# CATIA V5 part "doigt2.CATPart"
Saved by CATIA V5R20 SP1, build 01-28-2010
Part number: doigt2
Bounding box of the stored display mesh (mm): x -20 to -3, y -206.5 to -61.5, z -6 to 36.5
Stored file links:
  D:\thinkmotion-MPB\Dropbox\IAO_2011\MMS_GR1\0\IAO_2011_1470_mpeyrard\mpeyrard\mpeyrard\mpeyrard\IAO_2011_1470_mpeyrard\doigt2.CATPart
  D:\thinkmotion-MPB\Dropbox\IAO_2011\MMS_GR1\0\IAO_2011_1470_mpeyrard\mpeyrard\mpeyrard\mpeyrard\IAO_2011_1470_mpeyrard\mpeyrard.CATProduct
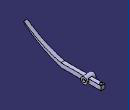
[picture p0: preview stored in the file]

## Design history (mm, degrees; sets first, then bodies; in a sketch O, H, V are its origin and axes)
External parameters (linked from other documents)
  External.Longueur_griffe = 70 mm
  External.Hauteur_griffe = 30 mm
Set1
  Line1: linked copy from another document
  Plane1: linked copy from another document
  Line2: linked copy from another document
  Line3: linked copy from another document
Body1 (main body)
  Sketch1 on yz-plane, origin (0, 0, 0), H (0, 1, 0), V (0, 0, 1)
    circle A1 centre (-90, 0) radius 6
    point P1 (-90, 0)
    reference projected point E1 (-90, 0) from Line1
    circle A2 centre (-90, 0) radius 3
    radius A1 = 6
    distance P1 E1 = 0
    radius A2 = 3
  Pad1: profile Sketch1, direction (-1, 0, 0), length 20, opposite side length -3
  Sketch2 on Plane1, origin (0, 0, 0), H (1, 0, 0), V (0, 1, 0)
    axis line L1 (-6.5, -65) -> (-14.0151, -65)
    point P1 (-6.5, -65)
    reference projected line E1 (0, -90) -> (0, -65) from Line2
    reference projected point E2 (0, -65) from Line3
    reference projected point E3 (0, -65) from Line3
    line L2 (-6.5, -61.5) -> (-13.5, -61.5)
    line L3 (-13.5, -61.5) -> (-13.5, -136.5)
    line L4 (-13.5, -136.5) -> (-6.5, -136.5)
    line L5 (-6.5, -136.5) -> (-6.5, -61.5)
    distance L1 E2 = 0
    distance P1 E3 = 6.5
    distance L5 P1 = 0
    distance L2 L1 = 3.5
    distance L3 L5 = 7
    length L3 = 75
    perpendicularity: E1 L1
    horizontal: L2 H, L4 H
    vertical: L3 V, L5 V
  Pad2: profile Sketch2, direction (0, 0, 1), length 4, mirrored extent
  Sketch3 on end face of Pad2, origin (-9.6581, -67.5598, 4), H (1, 0, 0), V (0, 1, 0)
    point P1 (-0.3419, 2.5598)
    reference projected point E1 (9.6581, 2.5598) from Line3
    reference projected line E2 (3.1581, 6.0598) -> (-3.8419, 6.0598) from edge [face of Pad2 from Sketch2.L2 | end face of Pad2]
    distance E1 P1 = 10
    distance P1 E2 = 3.5
  Hole1: placed by Sketch3, at (-10, -65, 4) direction (0, 0, -1), diameter 5, through (limit type 3)
  Sketch4 on face of Pad2 from Sketch2.L3, origin (-13.5, 0, 0), H (0, -1, 0), V (0, 0, 1)
    spline S1 through (136.5, -4) (171.5, 11) (206.5, 34)
    reference projected point E1 (136.5, -4) from vertex [start face of Pad2 | face of Pad2 from Sketch2.L3 | face of Pad2 from Sketch2.L4]
    line L1 (136.5, -4) -> (136.5, 4)
    point P1 (136.5, -4)
    point P2 (136.5, 4)
    reference projected point E2 (136.5, 4) from vertex [end face of Pad2 | face of Pad2 from Sketch2.L3 | face of Pad2 from Sketch2.L4]
    spline S2 through (206.5, 36.5) (171.5, 16) (136.5, 4)
    line L2 (206.5, 34) -> (206.5, 36.5)
    point P3 (206.5, 34)
    point P4 (206.5, 36.5)
    reference projected line E3 (61.5, -4) -> (136.5, -4) from edge [start face of Pad2 | face of Pad2 from Sketch2.L3]
    reference projected line E4 (61.5, 4) -> (136.5, 4) from edge [face of Pad2 from Sketch2.L3 | end face of Pad2]
    point P5 (136.5, -4)
    point P6 (206.5, 36.5)
    point P7 (206.5, 34)
    point P8 (136.5, 4)
    point P9 (171.5, 11)
    point P10 (171.5, 16)
    length L2 = 2.5
    distance L1 L2 = 70 {= External.Longueur_griffe}
    distance P9 L1 = 35 {= External.Longueur_griffe/2}
    distance P10 L1 = 35 {= External.Longueur_griffe/2}
    distance P9 P10 = 5 {= 5mm}
    distance P9 E3 = 15 {= External.Hauteur_griffe/2}
    distance P3 E4 = 30 {= External.Hauteur_griffe}
    coincidence: P5 E1, P5 P1, P2 E2, P8 P2, P7 P3, P6 P4
  Pad3: profile Sketch4, direction (1, 0, 0), up to face of Pad2 from Sketch2.L5
  Sketch5 on face of Pad2 from Sketch2.L5, origin (-6.5, -90.5209, 0.2701), H (0, 1, 0), V (0, 0, 1)
    point P1 (0.5209, -0.2701)
    reference projected circle E1 centre (0.5209, -0.2701) radius 3 from edge [face of Pad2 from Sketch2.L5 | face of Pad1 from Sketch1.A2]
    concentricity: E1 P1
  Hole2: placed by Sketch5, at (-6.5, -90, 0) direction (-1, 0, 0), diameter 6, through (limit type 3)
